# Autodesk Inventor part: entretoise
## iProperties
Author: chr
Shininess: 20.0
Angle Display Precision: 2
Document Length Units: 11269
Document Angle Units: 11283
Document Time Units: 11279
Document Mass Units: 11290
Document Length Units Precision: 3
Document Angle Units Precision: 2
Compacted: False
PropertySet Name: _Private Model Information
Created: 2002-03
Part Number: entretoise
Material: Par défaut
Document SubType Name: Modélisation
Designer: chr
Control State: 0
Master: False
Checked Out: False
PropertySet Name: Design Tracking Control
Density: 0.0
Volumn: 0.0
Area: 0.0
PropertySet Name: Model Information
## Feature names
1. Extrusion1
2. Extrusion2
3. Extrusion3
4. Extrusion4
5. Réseau circulaire1 [Circular Pattern]
6. Extrusion5
7. Extrusion6
8. Extrusion7
9. Réseau circulaire2 [Circular Pattern]
